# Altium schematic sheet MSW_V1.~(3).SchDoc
size B; Organization: ORGANIZATION; Address1: ADDRESS 1; Address2: ADDRESS 2; Address3: ADDRESS 3; Address4: ADDRESS 4; Revision: -; SheetNumber: 1; SheetTotal: 1; ENG_APP_DATE: --/--/--; DSN_APP_DATE: --/--/--; CHK_APP_DATE: --/--/--
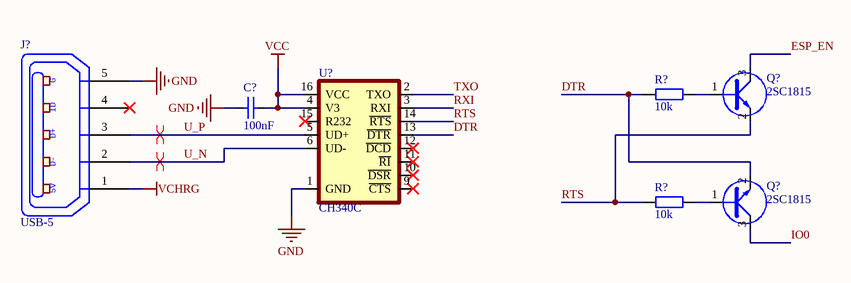
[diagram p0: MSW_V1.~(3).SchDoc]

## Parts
(Parts that share a designator on the sheet are numbered #1, #2 ... from top to bottom, then left to right.)
C?  100nF  [CAP_0603]
J?  USB-5  [USB-M1]
Q?#1  2SC1815  [SOT23D]
Q?#2  2SC1815  [SOT23D]
R?#1  10k  [RES-SMD-0603]
R?#2  10k  [RES-SMD-0603]
U?  CH340C  [SOP-16]

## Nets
GND: C?.1 J?.5(P5) U?.1(GND)
VCC: C?.2 U?.4(V3) U?.16(VCC)
VCHRG: J?.1(P1)
DTR: Q?#2.2(E) R?#1.2 U?.13(~{DTR})
ESP_EN: Q?#1.3(C)
IO0: Q?#2.3(C)
RTS: Q?#1.2(E) R?#2.2 U?.14(~{RTS})
RXI: U?.3(RXI)
TXO: U?.2(TXO)
U_N: J?.2(P2) U?.6(UD-)
U_P: J?.3(P3) U?.5(UD+)
NetQ?#1_1: Q?#1.1(B) R?#1.1
NetQ?#2_1: Q?#2.1(B) R?#2.1

Not connected (* = marked no-connect by the designer): J? 4(P4)*; U? 9(~{CTS})* 10(~{DSR})* 11(~{RI})* 12(~{DCD})* 15(R232)*

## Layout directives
differential pair: U_N, U_P

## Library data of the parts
C? = CapSMD: Capacitor; Value: 33p
J? = USB-5: Manufacturer: FCI; Manufacturer Part Number: 10118193-0001LF; Connector Type: USB - micro B; Number of Contacts: 5; Gender: Receptacle; Specifications: USB 2.0; .Creator: MM; .Checked PCB: RF
Q?#1 Q?#2 = C1815: NPN 600mW, ECB; Value: C1815
R?#1 R?#2 = Resistor - SMD: Resistor SMD; Manufacturer: Generic Components; Class: Passive
U? = CH340C: USB to serial chip CH340; MF: WCH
